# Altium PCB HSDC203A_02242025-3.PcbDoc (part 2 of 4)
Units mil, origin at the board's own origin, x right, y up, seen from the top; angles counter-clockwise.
Board outline 5612.98 x 3012.39 mil, 6 copper layers (Top Layer, GND1, Signal1, Power, GND2, Bottom Layer), stack 60.4 mil thick; 301 components, 211 nets, 1107 pads, 249 vias.
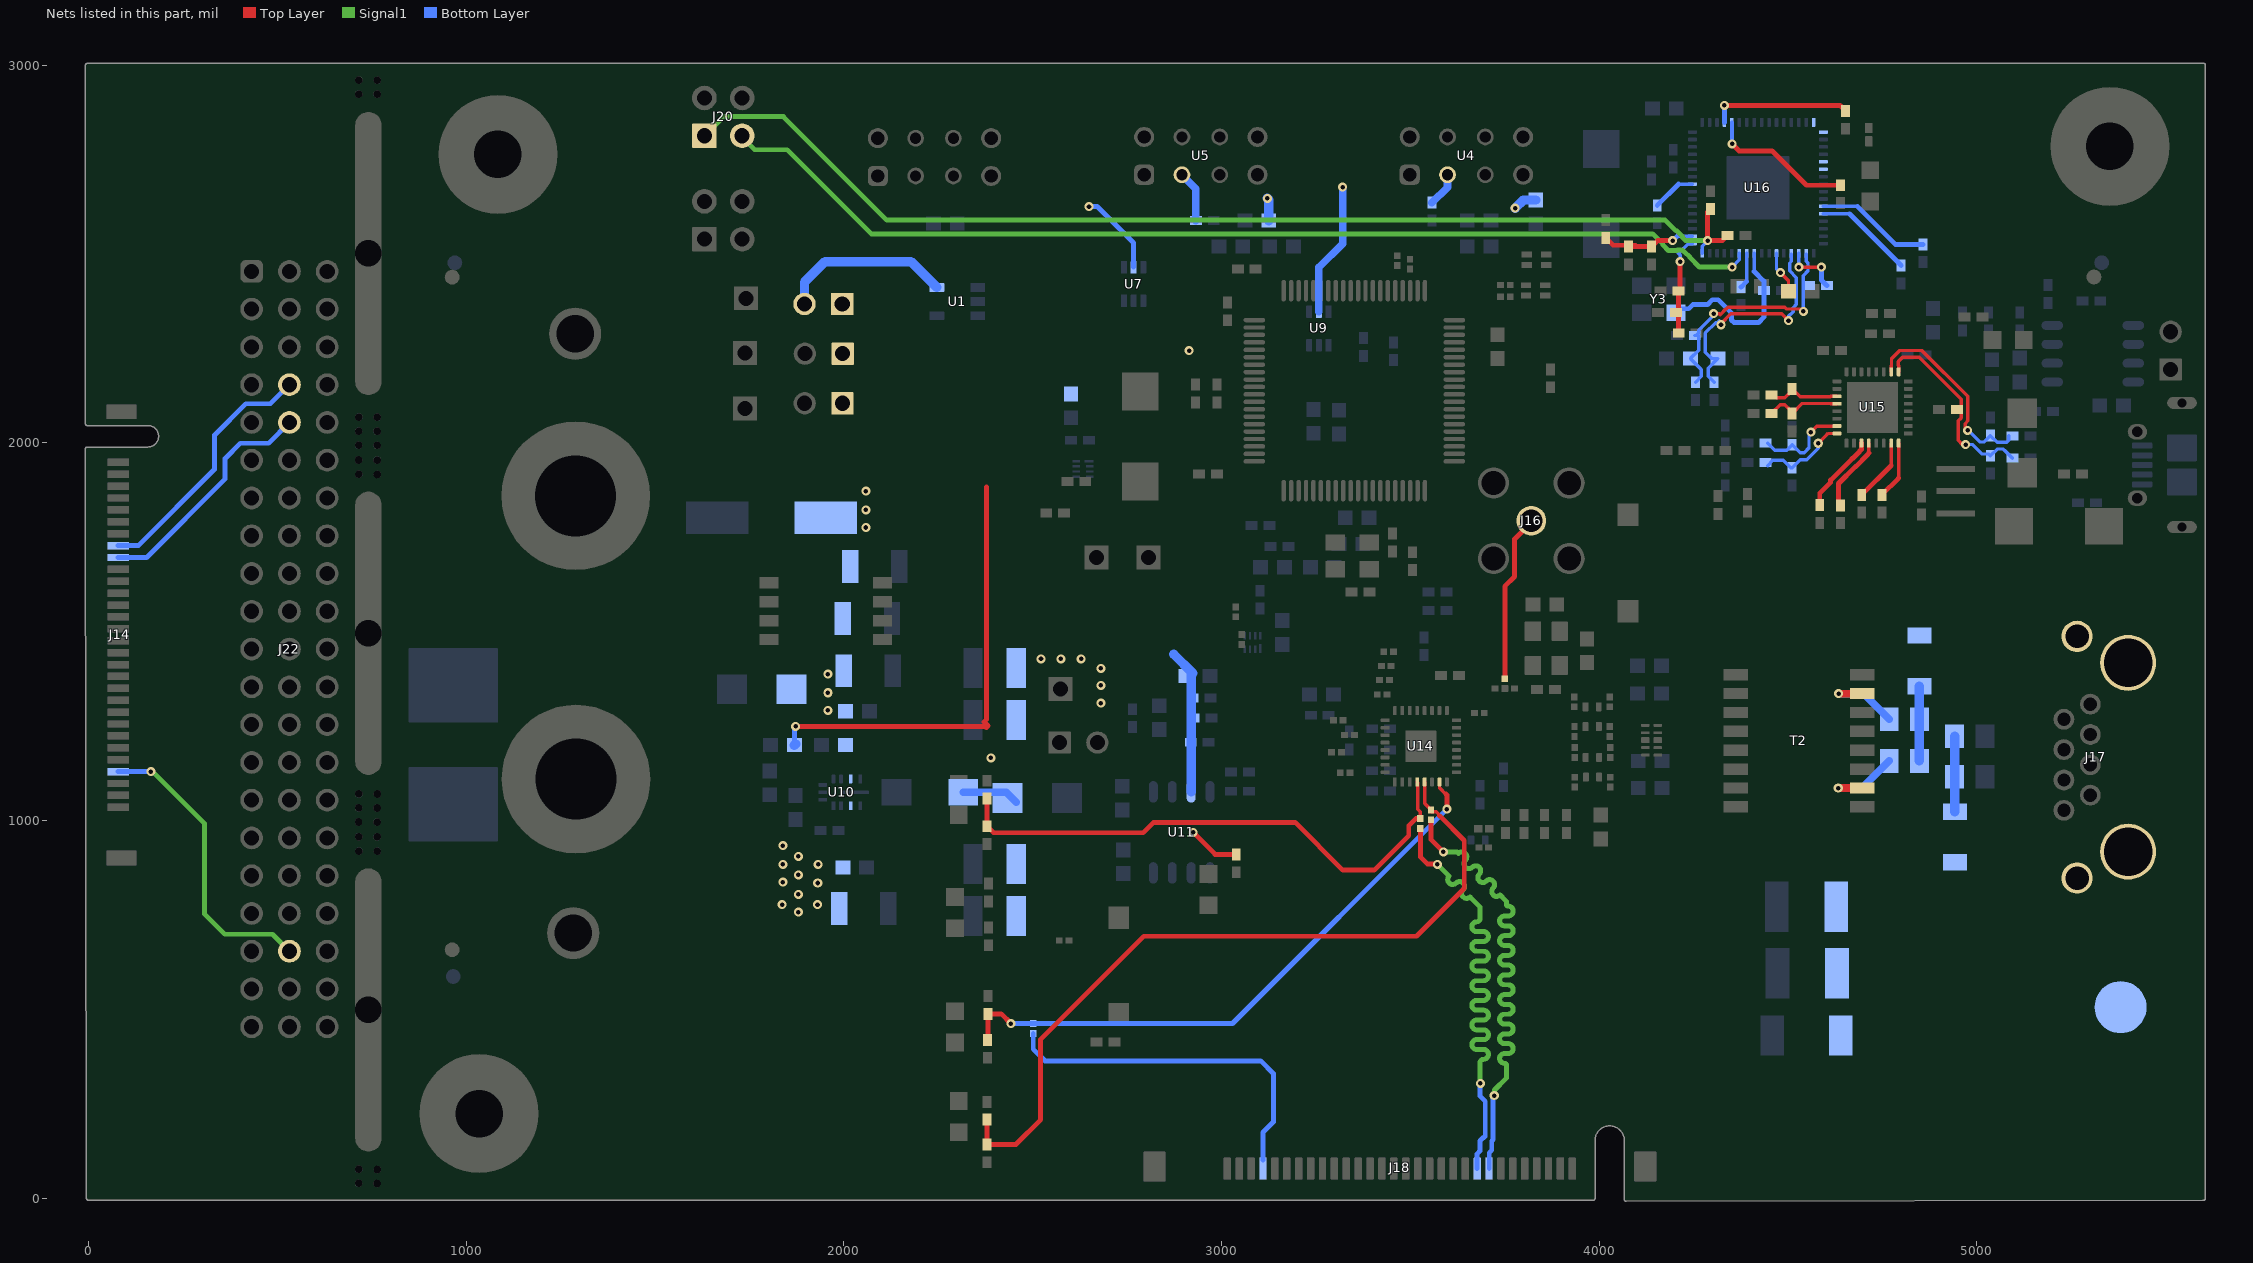
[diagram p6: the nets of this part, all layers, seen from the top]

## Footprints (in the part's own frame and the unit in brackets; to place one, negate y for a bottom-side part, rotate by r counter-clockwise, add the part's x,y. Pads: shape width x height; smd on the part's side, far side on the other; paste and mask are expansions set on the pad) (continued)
Sullins_PEC01SAAN [mm] "SULLINS"
  rect 1.6x1.6 hole 1: 1(0,0)
  silkscreen extent -1.4,-1.4 1.4,1.4, body extent -1.3,-1.3 1.3,1.3, height 8.38
SW_218-4LPST [mil] "CTS Components"
  rect 50x30 smd: 1(-150,75) 2(-150,25) 3(-150,-25) 4(-150,-75) 5(150,-75) 6(150,-25) 7(150,25) 8(150,75)
  silkscreen extent -114,-123 114,123, body extent -166,-123 166,123, height 104
TE_5-1814832-1 [mm] "SMA Straight PCB Socket Die Cast, TH"
  round 2 hole 1.5: 1(0,0)
  round 2.1 hole 1.6: 2(-2.54,2.54) 3(-2.54,-2.54) 4(2.54,-2.54) 5(2.54,2.54)
  silkscreen extent -3.2,-3.2 3.2,3.2, body extent -3.2,-3.2 3.2,3.2, height 9.5
TEC_1-406541-1 [mm] "TE Connectivity"
  round 1.4 hole 0.89: 1(3.56,-0.18) 2(2.54,1.6) 3(1.52,-0.18) 4(0.5,1.6) 5(-0.52,-0.18) 6(-1.54,1.6) 7(-2.56,-0.18) 8(-3.58,1.6)
  round 2.1 hole 1.57: 9(8.12,0.71) 10(-8.14,0.71)
  round 3.759 hole 3.251: 11(6.34,-2.72) 12(-6.36,-2.72)
  silkscreen extent -9.69,-8 9.69,8.06, body extent -9.33,-8 9.31,7.75, height 14.8
TI_Stacked_Overlay_Small [mil]
  silkscreen extent -418,-98 418,98
TSW-102-07-G-D [mm] "Samtec 100mil, 2x2, 230 mil above insulator"
  rrect6% 1.65x1.65 hole 1.016: 1(-1.27,-1.27)
  round 1.65 hole 1.016: 2(-1.27,1.27) 3(1.27,-1.27) 4(1.27,1.27)
  silkscreen extent -3.56,-2.54 2.54,2.54, body extent -2.54,-2.54 2.54,2.54, height 8.38
WEEE_Minimum [mil] "WEEElie bin"
  silkscreen extent -95,-172 99,104

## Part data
C1 C2 C5 C6 C23: library part CMP-0006356-2, "CAP, CERM, 0.1 uF, 50 V, +/- 10%, X7R, AEC-Q200 Grade 1, 0402", Cap_Case=0402, Manufacturer=MuRata, Supplier Part Number 1=490-10672-1-ND, TempCo=X7R, Tolerance_%=10%, Value1=Unknown, Value2=50V, ValueDisplayed=0.1uF
C3 C4 C43 C44: library part CMP-0007071-4, "CAP, CERM, 22 pF, 50 V, +/- 5%, C0G/NP0, AEC-Q200 Grade 1, 0603", Cap_Case=0603, Manufacturer=TDK, Supplier Part Number 1=445-5632-1-ND, TempCo=C0G/NP0, Tolerance_%=5%, Value1=Unknown, Value2=50V, ValueDisplayed=22pF
C7 C8 C90 C91: library part CMP-0083839-1, "CAP, CERM, 36 pF, 50 V,+/- 5%, C0G/NP0, 0402", Cap_Case=0402, Manufacturer="Samsung Electro-Mechanics", TempCo=C0G/NP0, Tolerance_%=5%, Value2=50V, ValueDisplayed=36pF
C9 C12: library part CMP-0006905-4, "CAP, CERM, 0.22 uF, 16 V, +80/-20%, Y5V, 0603", Cap_Case=0603, Manufacturer=Kemet, Supplier Part Number 1=399-1102-1-ND, TempCo=Y5V, Tolerance_%=80%, Value1=Unknown, Value2=16V, ValueDisplayed=0.22uF
C10: library part CMP-0007138-4, "CAP, CERM, 0.47 uF, 16 V, +/- 10%, X7R, AEC-Q200 Grade 1, 0603", Cap_Case=0603, Manufacturer=MuRata, Supplier Part Number 1=490-4775-1-ND, TempCo=X7R, Tolerance_%=10%, Value1=Unknown, Value2=16V, ValueDisplayed=0.47uF
C11: library part CMP-0007022-5, "CAP, CERM, 4.7 uF, 35 V, +/- 10%, X5R, 0603", Cap_Case=0603, Manufacturer=TDK, Supplier Part Number 1=445-9064-1-ND, TempCo=X5R, Tolerance_%=10%, Value1="0.003728 ohm", Value2=35V, ValueDisplayed=4.7uF
C13 C85: library part CMP-0011855-2, "CAP, TA, 10 uF, 35 V, +/- 10%, 0.125 ohm, SMD", Cap_Case=D, Manufacturer=AVX, Supplier Part Number 1=478-3337-1-ND, Tolerance_%=10%, Value1="0.125 ohm", Value2=35V, ValueDisplayed=10uF
C14 C15 C16 C47 C49 C57 C62 C65: library part CMP-0078241-1, "CAP, CERM, 0.1 µF, 10 V,+/- 10%, X7R, 0402", Cap_Case=0402, Manufacturer=Kemet, Supplier Part Number 1=399-3520-1-ND, TempCo=X7R, Tolerance_%=10%, Value2=10V, ValueDisplayed=0.1µF
C17 C83: library part CMP-0006254-2, "CAP, CERM, 1000 pF, 50 V, +/- 5%, C0G/NP0, 0402", Cap_Case=0402, Manufacturer=TDK, Supplier Part Number 1=445-13785-1-ND, TempCo=C0G/NP0, Tolerance_%=5%, Value1=Unknown, Value2=50V, ValueDisplayed=1000pF
C18: library part CMP-0011279-3, "CAP, AL, 100 uF, 50 V, +/- 20%, SMD", Cap_Case=HA0, Manufacturer=Chemi-Con, Supplier Part Number 1=565-2252-1-ND, Tolerance_%=20%, Value1=Unknown, Value2=50V, ValueDisplayed=100uF
C19 C21: library part CMP-0009162-2, "CAP, CERM, 4.7 uF, 50 V, +/- 10%, X7R, AEC-Q200 Grade 1, 1210", Cap_Case=1210_280, Manufacturer=TDK, Supplier Part Number 1=445-6999-1-ND, TempCo=X7R, Tolerance_%=10%, Value1="0.003166 ohm", Value2=50V, ValueDisplayed=4.7uF
C20 C22: library part CMP-0007094-5, "CAP, CERM, 0.22 uF, 50 V, +/- 10%, X7R, AEC-Q200 Grade 1, 0603", Cap_Case=0603, Manufacturer=TDK, Supplier Part Number 1=445-6926-1-ND, TempCo=X7R, Tolerance_%=10%, Value1="0.021699 ohm", Value2=50V, ValueDisplayed=0.22uF
C24: library part CMP-0009154-2, "CAP, CERM, 22 uF, 16 V, +/- 20%, X7R, AEC-Q200 Grade 1, 1210", Cap_Case=1210_280, Manufacturer=TDK, Supplier Part Number 1=445-5723-1-ND, TempCo=X7R, Tolerance_%=20%, Value1="0.002582 ohm", Value2=16V, ValueDisplayed=22uF
C25: library part CMP-0009155-2, "CAP, CERM, 10 uF, 25 V, +/- 20%, X7R, AEC-Q200 Grade 1, 1210", Cap_Case=1210, Manufacturer=TDK, Supplier Part Number 1=445-5720-1-ND, TempCo=X7R, Tolerance_%=20%, Value1=Unknown, Value2=25V, ValueDisplayed=10uF
C26: library part CMP-0007067-4, "CAP, CERM, 1 uF, 35 V, +/- 10%, X7R, AEC-Q200 Grade 1, 0603", Cap_Case=0603, Manufacturer=TDK, Supplier Part Number 1=445-174215-1-ND, TempCo=X7R, Tolerance_%=10%, Value1="0.005522 ohm", Value2=35V, ValueDisplayed=1uF
C27 C28 C29 C30: library part CMP-0080552-1, "CAP, CERM, 22 µF, 25 V,+/- 10%, X7R, AEC-Q200 Grade 1, 1210", Cap_Case=1210, Manufacturer="Taiyo Yuden", Supplier Part Number 1=587-5949-1-ND, TempCo=X7R, Tolerance_%=10%, Value2=25V, ValueDisplayed=22µF
C31 C37: library part CMP-0006620-2, "CAP, CERM, 1 uF, 35 V, +/- 20%, X5R, 0402", Cap_Case=0402, Manufacturer=MuRata, Supplier Part Number 1=490-10020-1-ND, TempCo=X5R, Tolerance_%=20%, Value1=Unknown, Value2=35V, ValueDisplayed=1uF
C32 C35 C38 C41: library part CMP-0007355-6, "CAP, CERM, 10 uF, 35 V, +/- 20%, X5R, 0603", Cap_Case=0603, Manufacturer=Murata, TempCo=X5R, Tolerance_%=20%, Value1=Unknown, Value2=35V, ValueDisplayed=10uF
C33 C34 C39 C40: library part CMP-0006526-2, "CAP, CERM, 2.2 uF, 16 V, +/- 10%, X6S, 0402", Cap_Case=0402, Manufacturer=MuRata, Supplier Part Number 1=GRM155C81C225KE11D-ND, TempCo=X6S, Tolerance_%=10%, Value1=Unknown, Value2=16V, ValueDisplayed=2.2uF
C36 C42: library part CMP-0006360-2, "CAP, CERM, 470 pF, 50 V, +/- 10%, X7R, AEC-Q200 Grade 1, 0402", Cap_Case=0402, Manufacturer=MuRata, Supplier Part Number 1=490-4913-1-ND, TempCo=X7R, Tolerance_%=10%, Value1=Unknown, Value2=50V, ValueDisplayed=470pF
C45 C55: library part CMP-0006862-5, "CAP, CERM, 0.1 uF, 10 V, +/- 10%, X7R, 0603", Cap_Case=0603, Manufacturer=Kemet, Supplier Part Number 1=399-1095-1-ND, TempCo=X7R, Tolerance_%=10%, Value1=Unknown, Value2=10V, ValueDisplayed=0.1uF
C46 C56: library part CMP-0007195-4, "CAP, CERM, 2000 pF, 50 V, +/- 5%, C0G/NP0, 0603", Cap_Case=0603, Manufacturer=MuRata, Supplier Part Number 1=490-1458-1-ND, TempCo=C0G/NP0, Tolerance_%=5%, Value1=Unknown, Value2=50V, ValueDisplayed=2000pF
C48 C50: library part CMP-0006340-2, "CAP, CERM, 10 uF, 6.3 V, +/- 20%, X5R, 0402", Cap_Case=0402, Manufacturer="Samsung Electro-Mechanics", TempCo=X5R, Tolerance_%=20%, Value1=Unknown, Value2=6.3V, ValueDisplayed=10uF
C51 C53 C60: library part CMP-0006227-2, "CAP, CERM, 0.01 uF, 16 V, +/- 10%, X7R, 0402", Cap_Case=0402, Manufacturer="Wurth Elektronik", Supplier Part Number 1=710-885012205031, TempCo=X7R, Tolerance_%=10%, Value1=Unknown, Value2=16V, ValueDisplayed=0.01uF
C52 C54: library part CMP-0064947-2, "CAP, CERM, 1 uF, 6.3 V,+/- 10%, X7R, 0402", Cap_Case=0402, Manufacturer=MuRata, Supplier Part Number 1=490-10024-1-ND, TempCo=X7R, Tolerance_%=10%, Value1=Unknown, Value2=6.3V, ValueDisplayed=1uF
C58 C59: library part CMP-0008579-2, "CAP, CERM, 1000 pF, 2000 V, +/- 10%, X7R, AEC-Q200 Grade 1, 1206", Cap_Case=1206, Manufacturer=Kemet, Supplier Part Number 1=399-12976-1-ND, TempCo=X7R, Tolerance_%=10%, Value1=Unknown, Value2=2000V, ValueDisplayed=1000pF
C61 C63: library part CMP-0009295-2, "CAP, CERM, 4700 pF, 2000 V, +/- 10%, X7R, 1812", Cap_Case=1812, Manufacturer=AVX, Supplier Part Number 1=478-3003-1-ND, TempCo=X7R, Tolerance_%=10%, Value1=Unknown, Value2=2000V, ValueDisplayed=4700pF
C64: library part CMP-0011708-2, "CAP, TA, 4.7 uF, 35 V, +/- 10%, 1.3 ohm, SMD", Cap_Case=D, Manufacturer=Vishay-Sprague, Supplier Part Number 1=718-1084-1-ND, Tolerance_%=10%, Value1="1.3 ohm", Value2=35V, ValueDisplayed=4.7uF
C66 C67 C68 C69 C72 C73: library part CMP-0860896-1, "CAP, CERM, 22 pF, 50 V,+/- 5%, C0G/NP0, 0402", Cap_Case=0402, Manufacturer=TDK, TempCo=C0G/NP0, Tolerance_%=5%, Value2=50V, ValueDisplayed=22pF
C70 C71 C75 C76: library part CMP-0007074-4, "CAP, CERM, 10 pF, 50 V, +/- 5%, C0G/NP0, 0603", Cap_Case=0603, Manufacturer=TDK, Supplier Part Number 1=445-12387-1-ND, TempCo=C0G/NP0, Tolerance_%=5%, Value1=Unknown, Value2=50V, ValueDisplayed=10pF
C74 C77 C78 C86 C87: library part CMP-0085850-1, "CAP, CERM, 0.1 µF, 16 V,+/- 10%, X7R, 0402", Cap_Case=0402, Manufacturer=Walsin, TempCo=X7R, Tolerance_%=10%, Value2=16V, ValueDisplayed=0.1µF
C79 C80: library part CMP-0860833-1, "CAP, CERM, 33 pF, 50 V,+/- 5%, C0G/NP0, AEC-Q200 Grade 1, 0402", Cap_Case=0402, Manufacturer=MuRata, TempCo=C0G/NP0, Tolerance_%=5%, Value2=50V, ValueDisplayed=33pF
C81 C84: library part CMP-0860899-1, "CAP, CERM, 0.22 µF, 50 V,+/- 10%, X5R, 0603", Cap_Case=0603, Manufacturer="Samsung Electro-Mechanics", TempCo=X5R, Tolerance_%=10%, Value2=50V, ValueDisplayed=0.22µF
C82: library part CMP-0007096-4, "CAP, CERM, 0.47 uF, 50 V, +/- 10%, X7R, AEC-Q200 Grade 1, 0603", Cap_Case=0603, Manufacturer=TDK, Supplier Part Number 1=810-CGA3E3X7R1H474K080AB, TempCo=X7R, Tolerance_%=10%, Value1="0.01064 ohm", Value2=50V, ValueDisplayed=0.47uF
C88: library part CMP-0093676-1, "Chip Multilayer Ceramic Capacitors for General Purpose, 0402, 2.2uF, X7R, 15%, 10%, 10V", Manufacturer=Murata, Operating Temperature Range="-55°C to +125°C", TempCo=15%, Temperature Characteristic=X7R, Tolerance_%=10%, ValueDisplayed=2.2uF
C89 C92 C93 C94 C95 C96 C97 C98: library part CMP-0009653-3, "CAP, CERM, 330 pF, 50 V, +/- 10%, X7R, AEC-Q200 Grade 1, 0201", Cap_Case=0201_033, Manufacturer=TDK, Supplier Part Number 1=445-12111-1-ND, TempCo=X7R, Tolerance_%=10%, Value1="8.05302 ohm", Value2=50V, ValueDisplayed=330pF
D1 D6: library part CMP-0002934-2, "LED, Rg, SMD", Color=RG, Manufacturer=Avago, Supplier Part Number 1=516-1419-1-ND, Value1=W, Value2=2.2V
D2 D3 D7: library part CMP-0028762-2, "Diode, Schottky, 60 V, 1 A, AEC-Q101, SMA", Manufacturer="ON Semiconductor", Value1=1A, Value2=0.51V
D4: library part CMP-0077734-1, "LED, Orange, SMD", Color=Orange, Manufacturer=Kingbright, Power_TotalModule=75mW, Supplier Part Number 1=754-1103-1-ND, Value1=.075W, Value2=2.1V
D5 LD1 LD2 LD3 LD4 LD5 LD6: library part CMP-0002917-2, "LED, Green, SMD", Color=Green, Manufacturer=Everlight, Value1=W, Value2=2.1V
FID1 FID2 FID3 FID4 FID5 FID6: library part CMP-0077181-1, "Fiducial mark.  There is nothing to buy or mount.", Manufacturer=N/A
H1 H2 H3: library part CMP-0003617-1, "Machine Screw, Round, #4-40 x 1/4, Nylon, Philips panhead", Manufacturer="B&F Fastener Supply", Supplier Part Number 1=H542-ND
H5 H6 H7 H8: library part CMP-0003611-1, "Standoff, Hex, 1\"L #4-40 Nylon", Manufacturer=Keystone, Supplier Part Number 1=36-1902E-ND
J1: library part CMP-0054706-1, "Header, 1x1, Tin, TH", Color=Black, Current_A=3A, Manufacturer="Sullins Connector Solutions", PartNumber=PEC01SAAN, Supplier Part Number 1=S1012E-01-ND, Voltage_V=1.8kV
J2 J10 J11 J12 J13: library part CMP-0054706-1, "Header, 1x1, Tin, TH", Color=Black, Current_A=3A, Manufacturer="Sullins Connector Solutions", Supplier Part Number 1=S1012E-01-ND, Voltage_V=1.8kV
J3 J20: library part CMP-0075404-1, "Header, 100mil, 2x2, Gold, TH", Color=Black, Current_A=6.3A, Manufacturer=Samtec, Supplier Part Number 1=SAM1028-02-ND, Voltage_V=550V
J4 J5 J24: library part CMP-0055113-1, "Terminal, Turret, TH, Double", Manufacturer=Keystone, Supplier Part Number 1=36-1502-2-ND
J6 J7 J8 J9 J23: library part CMP-0002337-1, "Header, 100mil, 2x1, Tin, TH", Color=Black, Current_A=3A, Manufacturer="Sullins Connector Solutions", Supplier Part Number 1=S1012E-02-ND, Voltage_V=1.8kV
J14: library part CMP-0055619-1, "Receptacle, 0.8mm, 30x2, Tin, Edge mount", Color=Black, Current_A=2.2A, Manufacturer=Samtec, Supplier Part Number 1=33R2583, Voltage_V=200V
J15 J21: library part CMP-0055165-2, "Standard Banana Jack, Uninsulated, 5.5mm", Manufacturer=Keystone, Supplier Part Number 1=36-575-4-ND
J16: library part CMP-0054990-1, "SMA Straight PCB Socket Die Cast, 50 Ohm, TH", Manufacturer="TE Connectivity", Supplier Part Number 1=A97594-ND
J17: library part CMP-0054918-1, "RJ45, No LED, tab up, R/A, TH", Color=Black, Manufacturer="TE Connectivity", Supplier Part Number 1=A97716-ND
J18: library part CMP-0055720-1, "Receptacle, 0.8mm, 30x2, Gold, Edge Mount", Current_A=2.2A, Manufacturer=Samtec, Supplier Part Number 1=ERF8-030-01-L-D-EM2-TR-ND, Voltage_V=200V
J19: library part CMP-0055301-1, "Connector, Receptacle, Micro-USB Type AB, R/A, Bottom Mount SMT", Manufacturer=Molex, Supplier Part Number 1=WM17143CT-ND
J22: library part CMP-0084401-1, "Header, 2.54mm, 21x3, Gold, TH", Color=Natural, Manufacturer=Samtec
L1: library part CMP-0056947-1, "Inductor, Shielded, Ferrite, 10 uH, 2.75 A, 0.128 ohm, SMD", Manufacturer=Bourns, Supplier Part Number 1=652-SRP5030T-100M, Value1="0.128 ohm", Value2=2.75A, ValueDisplayed=10uH
Logo1: library part CMP-0074844-1
Logo2: library part CMP-0074838-1, "Texas Instrument Corporate Signature"
Logo3: library part CMP-0074847-1, "FCC_disclaimer"
Logo4: library part CMP-0074769-1
R1 R2: library part CMP-0025750-4, "RES, 200 k, 5%, 0.1 W, AEC-Q200 Grade 0, 0603", Manufacturer=Vishay-Dale, Power_W=100mW, Supplier Part Number 1=541-200KGCT-ND, TempCo="200 ppm/C", Tolerance_%=5%, Value2=0.1W, Value_Code=200k
R3 R4: library part CMP-0025879-3, "RES, 2.2 k, 5%, 0.1 W, AEC-Q200 Grade 0, 0603", Manufacturer=Panasonic, Power_W=100mW, Supplier Part Number 1=P2.2KGCT-ND, TempCo="200 ppm/C", Tolerance_%=5%, Value2=0.1W, Value_Code=2k20, ValueDisplayed=2.2k
R5: library part CMP-0021993-5, "RES, 102, 1%, 0.1 W, AEC-Q200 Grade 0, 0603", Manufacturer=Vishay-Dale, Power_W=100mW, Supplier Part Number 1=541-102HCT-ND, TempCo="100 ppm/C", Tolerance_%=1%, Value2=0.1W, Value_Code=102R, ValueDisplayed=102
R6 R27 R30 R32 R35: library part CMP-0025874-4, "RES, 0, 5%, 0.1 W, AEC-Q200 Grade 0, 0603", Manufacturer=Panasonic, Power_W=100mW, Supplier Part Number 1=P0.0GCT-ND, TempCo="600 ppm/C", Tolerance_%=5%, Value2=0.1W, Value_Code=0000, ValueDisplayed=0
R7: library part CMP-0025785-4, "RES, 330, 5%, 0.1 W, AEC-Q200 Grade 0, 0603", Manufacturer=Vishay-Dale, Power_W=100mW, Supplier Part Number 1=541-330GCT-ND, TempCo="200 ppm/C", Tolerance_%=5%, Value2=0.1W, Value_Code=330R, ValueDisplayed=330
R8 R9 R10 R11 R109 R110: library part CMP-0026992-3, "RES, 0, 5%, 0.1 W, AEC-Q200 Grade 0, 0402", Manufacturer=Panasonic, Power_W=100mW, Supplier Part Number 1=P0.0JCT-ND, TempCo="600 ppm/C", Tolerance_%=5%, Value2=0.1W, Value_Code=0000, ValueDisplayed=0
R12 R26: library part CMP-0022237-4, "RES, 24.9 k, 1%, 0.1 W, AEC-Q200 Grade 0, 0603", Manufacturer=Vishay-Dale, Power_W=100mW, Supplier Part Number 1=541-24.9KHCT-ND, TempCo="100 ppm/C", Tolerance_%=1%, Value2=0.1W, Value_Code=24k9, ValueDisplayed=24.9k
R13 R23: library part CMP-0026822-3, "RES, 0, 5%, 0.063 W, AEC-Q200 Grade 0, 0402", Manufacturer=Vishay-Dale, Power_W=63mW, Supplier Part Number 1=541-0.0JCT-ND, TempCo="200 ppm/C", Tolerance_%=5%, Value2=0.063W, Value_Code=0000, ValueDisplayed=0
R14 R15 R16 R17 R49: library part CMP-0027127-1, "RES, 470, 5%, 0.05 W, 0201", Manufacturer="Yageo America", Power_W=50mW, Supplier Part Number 1=311-470NCT-ND, TempCo="200 ppm/C", Tolerance_%=5%, Value2=0.05W, Value_Code=470R, ValueDisplayed=470
R18 R19 R37 R40 R42 R78 R96 R97 R98 R99 R100 R101 R102 R103 R104 R107 R108: library part CMP-0027008-4, "RES, 0, 5%, 0.05 W, 0201", Manufacturer=Vishay-Dale, Power_W=50mW, Supplier Part Number 1=72M6743, TempCo=ppm/C, Tolerance_%=5%, Value2=0.05W, Value_Code=0000, ValueDisplayed=0
R20 R77: library part CMP-0026085-3, "RES, 1.40 k, 1%, 0.063 W, AEC-Q200 Grade 0, 0402", Manufacturer=Vishay-Dale, Power_W=63mW, Supplier Part Number 1=541-1.40KLCT-ND, TempCo="100 ppm/C", Tolerance_%=1%, Value2=0.063W, Value_Code=1k40, ValueDisplayed=1.40k
R21 R81: library part CMP-0026100-2, "RES, 1.00 M, 1%, 0.063 W, AEC-Q200 Grade 0, 0402", Manufacturer=Vishay-Dale, Power_W=63mW, Supplier Part Number 1=541-1.00MLCT-ND, TempCo="100 ppm/C", Tolerance_%=1%, Value2=0.063W, Value_Code=1M00, ValueDisplayed=1.00M
R22 R79 R93: library part CMP-0026935-3, "RES, 47 k, 5%, 0.063 W, AEC-Q200 Grade 0, 0402", Manufacturer=Vishay-Dale, Power_W=63mW, Supplier Part Number 1=541-47KJCT-ND, TempCo="200 ppm/C", Tolerance_%=5%, Value2=0.063W, Value_Code=47k0, ValueDisplayed=47k
R24: library part CMP-0023343-3, "RES, 0, 1%, 0.1 W, AEC-Q200 Grade 0, 0603", Manufacturer="Stackpole Electronics Inc", Power_W=100mW, Supplier Part Number 1=RMCF0603ZT0R00CT-ND, TempCo=ppm/C, Tolerance_%=1%, Value2=0.1W, Value_Code=0
R25: library part CMP-0021990-4, "RES, 100 k, 1%, 0.1 W, AEC-Q200 Grade 0, 0603", Manufacturer=Vishay-Dale, Power_W=100mW, Supplier Part Number 1=541-100KHCT-ND, TempCo="100 ppm/C", Tolerance_%=1%, Value2=0.1W, Value_Code=100k
R28 R33: library part CMP-0026768-2, "RES, 100 k, 0.5%, 0.063 W, AEC-Q200 Grade 0, 0402", Manufacturer=Vishay-Dale, Power_W=63mW, Supplier Part Number 1=541-100KAVCT-ND, TempCo="50 ppm/C", Tolerance_%=0.5%, Value2=0.063W, Value_Code=100k
R29 R34 R53 R55 R57 R58 R86 R87: library part CMP-0026934-3, "RES, 470, 5%, 0.063 W, AEC-Q200 Grade 0, 0402", Manufacturer=Vishay-Dale, Power_W=63mW, Supplier Part Number 1=541-470JCT-ND, TempCo="200 ppm/C", Tolerance_%=5%, Value2=0.063W, Value_Code=470R, ValueDisplayed=470
R31 R36: library part CMP-0026036-3, "RES, 165 k, 1%, 0.063 W, AEC-Q200 Grade 0, 0402", Manufacturer=Vishay-Dale, Power_W=63mW, Supplier Part Number 1=541-165KLCT-ND, TempCo="100 ppm/C", Tolerance_%=1%, Value2=0.063W, Value_Code=165k
R38 R94 R95: library part CMP-0027004-2, "RES, 0, 5%, 0.063 W, 0402", Manufacturer="Yageo America", Power_W=63mW, Supplier Part Number 1=311-0.0JRCT-ND, TempCo="200 ppm/C", Tolerance_%=5%, Value2=0.063W, Value_Code=0000, ValueDisplayed=0
R39: library part CMP-0026727-1, "RES, 1.00 M, 1%, 0.063 W, 0402", Manufacturer="Yageo America", Power_W=63mW, Supplier Part Number 1=311-1.00MLRCT-ND, TempCo="100 ppm/C", Tolerance_%=1%, Value2=0.063W, Value_Code=1M00, ValueDisplayed=1.00M
R41 R88: library part CMP-0025697-4, "RES, 0, 5%, 0.1 W, AEC-Q200 Grade 0, 0603", Manufacturer=Vishay-Dale, Power_W=100mW, Supplier Part Number 1=541-0.0GCT-ND, TempCo="200 ppm/C", Tolerance_%=5%, Value2=0.1W, Value_Code=0000, ValueDisplayed=0
R43 R44 R45 R46: library part CMP-0021425-3, "RES, 75.0, 1%, 0.125 W, AEC-Q200 Grade 0, 0805", Manufacturer=Vishay-Dale, Power_W=125mW, Supplier Part Number 1=541-75.0CCT-ND, TempCo="100 ppm/C", Tolerance_%=1%, Value2=0.125W, Value_Code=75R0, ValueDisplayed=75.0
R47: library part CMP-0026890-5, "RES, 2.2 k, 5%, 0.063 W, AEC-Q200 Grade 0, 0402", Manufacturer=Vishay-Dale, Power_W=63mW, Supplier Part Number 1=541-2.2KJCT-ND, TempCo="200 ppm/C", Tolerance_%=5%, Value2=0.063W, Value_Code=2k20, ValueDisplayed=2.2k
R48: library part CMP-0026515-2, "RES, 6.49 k, 1%, 0.063 W, AEC-Q200 Grade 0, 0402", Manufacturer=Vishay-Dale, Power_W=63mW, Supplier Part Number 1=541-6.49KLCT-ND, TempCo="100 ppm/C", Tolerance_%=1%, Value2=0.063W, Value_Code=6k49, ValueDisplayed=6.49k
R50: library part CMP-0065361-1, "RES, 0, 5%, .05 W, AEC-Q200 Grade 0, 0201", Manufacturer=Panasonic, Power_W=50mW, Supplier Part Number 1=P15979CT-ND, TempCo=ppm/C, Tolerance_%=5%, Value2=.05W, Value_Code=0000, ValueDisplayed=0
R51: library part CMP-0016200-2, "RES, 10 M, 5%, 0.5 W, 2010", Manufacturer="TT Electronics/IRC", Power_W=500mW, Supplier Part Number 1=756-HVC2010-10MJT3, TempCo="100 ppm/C", Tolerance_%=5%, Value2=0.5W, Value_Code=10M0, ValueDisplayed=10M
R52 R111 R112 R113: library part CMP-0120020-1, "0 Ohms Jumper Chip Resistor 0402 (1005 Metric) Metal Element", Digikey Part Number=36-5113-1-ND, Manufacturer="Keystone Electronics", Mouser Part Number=534-5113, Operating Temperature Range=to
R54 R56 R59 R60 R115: library part CMP-0026756-1, "RES, 1.50 k, 1%, 0.063 W, AEC-Q200 Grade 0, 0402", Manufacturer="Stackpole Electronics Inc", Power_W=63mW, Supplier Part Number 1=RMCF0402FT1K50CT-ND, TempCo="100 ppm/C", Tolerance_%=1%, Value2=0.063W, Value_Code=1k50, ValueDisplayed=1.50k
R61 R106: library part CMP-0026088-3, "RES, 1.50 k, 1%, 0.063 W, AEC-Q200 Grade 0, 0402", Manufacturer=Vishay-Dale, Power_W=63mW, Supplier Part Number 1=541-1.50KLCT-ND, TempCo="100 ppm/C", Tolerance_%=1%, Value2=0.063W, Value_Code=1k50, ValueDisplayed=1.50k
R62: library part CMP-0026825-5, "RES, 10 k, 5%, 0.063 W, AEC-Q200 Grade 0, 0402", Manufacturer=Vishay-Dale, Power_W=63mW, Supplier Part Number 1=541-10KJCT-ND, TempCo="200 ppm/C", Tolerance_%=5%, Value2=0.063W, Value_Code=10k0, ValueDisplayed=10k
R63 R66 R76 R80: library part CMP-0026888-3, "RES, 27, 5%, 0.063 W, AEC-Q200 Grade 0, 0402", Manufacturer=Vishay-Dale, Power_W=63mW, Supplier Part Number 1=541-27JCT-ND, TempCo="200 ppm/C", Tolerance_%=5%, Value2=0.063W, Value_Code=27R0, ValueDisplayed=27
R64 R65 R67 R68 R71 R72: library part CMP-0026880-3, "RES, 22, 5%, 0.063 W, AEC-Q200 Grade 0, 0402", Manufacturer=Vishay-Dale, Power_W=63mW, Supplier Part Number 1=541-22JCT-ND, TempCo="200 ppm/C", Tolerance_%=5%, Value2=0.063W, Value_Code=22R0, ValueDisplayed=22
R69 R70 R73 R74 R82 R83 R84 R85: library part CMP-0026027-3, "RES, 15.0 k, 1%, 0.063 W, AEC-Q200 Grade 0, 0402", Manufacturer=Vishay-Dale, Power_W=63mW, Supplier Part Number 1=541-15.0KLCT-ND, TempCo="100 ppm/C", Tolerance_%=1%, Value2=0.063W, Value_Code=15k0, ValueDisplayed=15.0k
R75: library part CMP-0026908-3, "RES, 33, 5%, 0.063 W, AEC-Q200 Grade 0, 0402", Manufacturer=Vishay-Dale, Power_W=63mW, Supplier Part Number 1=541-33JCT-ND, TempCo="200 ppm/C", Tolerance_%=5%, Value2=0.063W, Value_Code=33R0, ValueDisplayed=33
R89: library part CMP-0026881-2, "RES, 240 k, 5%, 0.063 W, AEC-Q200 Grade 0, 0402", Manufacturer=Vishay-Dale, Power_W=63mW, Supplier Part Number 1=541-240KJCT-ND, TempCo="200 ppm/C", Tolerance_%=5%, Value2=0.063W, Value_Code=240k
R90 R92: library part CMP-0026877-2, "RES, 220 k, 5%, 0.063 W, AEC-Q200 Grade 0, 0402", Manufacturer=Vishay-Dale, Power_W=63mW, Supplier Part Number 1=541-220KJCT-ND, TempCo="200 ppm/C", Tolerance_%=5%, Value2=0.063W, Value_Code=220k
R91: library part CMP-0026840-2, "RES, 150 k, 5%, 0.063 W, AEC-Q200 Grade 0, 0402", Manufacturer=Vishay-Dale, Power_W=63mW, Supplier Part Number 1=541-150KJCT-ND, TempCo="200 ppm/C", Tolerance_%=5%, Value2=0.063W, Value_Code=150k
R105: library part CMP-0027010-2, "RES, 2.2 k, 5%, 0.05 W, 0201", Manufacturer=Vishay-Dale, Power_W=50mW, Supplier Part Number 1=541-2.2KAGCT-ND, TempCo="200 ppm/C", Tolerance_%=5%, Value2=0.05W, Value_Code=2k20, ValueDisplayed=2.2k
R114: library part CMP-0026237-2, "RES, 2.49 k, 1%, 0.063 W, AEC-Q200 Grade 0, 0402", Manufacturer=Vishay-Dale, Power_W=63mW, Supplier Part Number 1=541-2.49KLCT-ND, TempCo="100 ppm/C", Tolerance_%=1%, Value2=0.063W, Value_Code=2k49, ValueDisplayed=2.49k
S1: library part CMP-0002128-2, "Switch, Slide, SPST 4 poles, SMT", CurrentRating_mA=25A, Manufacturer="CTS Electrocomponents", Supplier Part Number 1=CT2184LPST-ND
S2 S3: library part CMP-0002170-2, "Switch, Normally open, 2.3N force, 200k operations, SMD", CurrentRating_mA=1.001kA, Manufacturer="C&K Components"
SH-J1 SH-J2 SH-J3 SH-J4: library part CMP-0078738-1, "Single Operation 2.54mm Pitch Open Top Jumper Socket", Manufacturer=Harwin, Supplier Part Number 1=952-2881-ND
T2: library part CMP-0030425-2, "Transformer, 350 uH, SMT", Manufacturer="Pulse Engineering", Supplier Part Number 1=553-2208-1-ND, ValueDisplayed=350uH
U1: library part CMP-0051649-3, "Automotive Catalog Single Inverter, DBV0005A, LARGE T&R", Alternate Manufacturer="Texas Instruments", F @ Nom Voltage(Max)(Mhz)=150, Generic Part Number=SN74LVC1G04-Q1, ICC @ Nom Voltage(Max)(mA)=0.01, Operating Temperature Range="-40 to 125 C", Rating=Automotive, tpd @ Nom Voltage(Max)(ns)=7.5,5.2,4.2,3.7, Voltage(Nom)(V)=1.8,2.5,3.3,5
U2 U3: library part CMP-0066434-1, "Dual Bidirectional Multi-Voltage Level Translator, DQE0008A (X2SON-8)", Alternate Manufacturer="Texas Instruments"
U4 U5: library part CMP-0079203-2, "Fiber Optic Receiver 5MBd, TH", Manufacturer="Broadcom Limited"
U6: library part CMP-0079202-2, "Fiber Optic Transmitter 820nm, TH", Manufacturer="Broadcom Limited"
U7 U9: library part CMP-0860319-1, "1-ch, 2:1 general-purpose analog multiplexer with 1.8-V logic control, DCK0006A (SOT-SC70-6)", Alternate Manufacturer="Texas Instruments", Operating Temperature Range="-40 to 125 C", Rating=Catalog
U8: library part CMP-0038965-1, "25 MHz Mixed Signal Microcontroller with 128 KB Flash, 8192 B SRAM and 63 GPIOs, -40 to 85 degC, 80-pin QFP (PN), Green (RoHS & no Sb/Br)", Frequency(MHz)=25, Manufacturer="Texas Instruments", Temp Sensor=Yes
U10: library part CMP-0081171-4, "3.8-V to 36-V 2-A Synchronous Step-Down Voltage Regulator, RNX0012B (VQFN-HR-12)", Alternate Manufacturer="Texas Instruments", Alternate PartNumber=LMR33620ARNXR, Operating Temperature Range="-40 to 125 C", Rating=Catalog
U11 U12: library part CMP-0036447-1, "Single Output Low Noise LDO, 500 mA, Adjustable 1.3 to 6.5 V Output, 2.5 to 16 V Input, 8-pin SOIC (D), -40 to 125 degC, Green (RoHS & no Sb/Br)", Manufacturer="Texas Instruments", Rating=Catalog
U13: library part CMP-0073613-3, "4-Channel Ultra-Low-Capacitance IEC ESD Protection Diode, DQA0010A (USON-10)", Alternate Manufacturer="Texas Instruments"
U14: library part CMP-0124715-1, "Deterministic, Low-Latency, Low-Power, 10/100 Mbps, Industrial Ethernet PHY", Manufacturer="Texas Instruments", Max Supply Voltage=3.6V, Min Supply Voltage=1.62V, Operating Temperature Range="-40°C to +85°C"
U15: library part CMP-0033743-2, "4-Port Full-Speed USB Hub, 3.3V, -40 to 85 degC, 32-Pin QFN (RHB), Green (RoHS & no Sb/Br)", Manufacturer="Texas Instruments", Supply Voltage(s)(V)=3.3
U16: library part CMP-0039268-4, "16-Bit Ultra-Low-Power Microcontroller, 128KB Flash, 8KB RAM, USB, 12Bit ADC, 2 USCIs, 32Bit HW MPY, RGC0064B (VQFN-64)", Frequency(MHz)=25, Manufacturer="Texas Instruments", Operating Temperature Range="-40 to 85 C", Rating=Catalog, Temp Sensor=Yes
XF1: library part CMP-0077258-1, "FUSE HLDR CARTRIDGE 125V 5A SMD", Manufacturer=Schurter, Supplier Part Number 1=486-1991-ND
XTAL1: library part CMP-0079863-1, "Crystal, 25 MHz, 20 ppm, AEC-Q200 Grade 1, SMD", Frequency_Fixed=25MHz, Frequency Stability="50 ppm", Frequency Tolerance="20 ppm", Manufacturer="ECS Inc.", Supplier Part Number 1=XC2151CT-ND
Y1 Y3: library part CMP-0004637-3, "Crystal, 24 MHz, 20pF, SMD", Frequency_Fixed=24MHz, Frequency Stability=+/-100ppm, Manufacturer="ECS Inc.", Supplier Part Number 1=XC1826CT-ND
Y2: library part CMP-0006147-4, "Resonator, 6 MHz, 15pF SMD", Frequency_Fixed=6MHz, Frequency Stability="+/-0.2 %", Manufacturer=MuRata, Supplier Part Number 1=490-1218-1-ND
ZZ1: library part CMP-0077236-1
ZZ2: library part CMP-0077237-1
ZZ3: library part CMP-0077238-1
ZZ4: library part CMP-0077238-1, "These assemblies must comply with workmanship standards IPC-A-610 Class 2, unless otherwise specified."

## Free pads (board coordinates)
  round 20 hole 20 unplated: 1(715.26,39.72) 1(715.26,996.48) 1(715.26,1033.93) 1(715.26,1993.82) 1(715.26,2031.27) 1(715.49,957.62) 1(715.49,1954.96) 1(715.49,2923.58) 1(715.85,76.79) 1(715.85,1071) 1(715.85,2068.34) 1(716.04,919.57) 1(716.04,1916.9) 1(716.08,2960.65) 1(764.47,39.37) 1(764.47,996.12) 1(764.47,1033.58) 1(764.47,1993.46) 1(764.47,2030.92) 1(764.7,957.27) 1(764.7,1954.6) 1(764.7,2923.23) 1(765.06,76.44) 1(765.06,1070.65) 1(765.06,2067.99) 1(765.26,919.21) 1(765.26,1916.55) 1(765.29,2960.3)
  oval 70x750 hole 70 slot 750 at 90 deg unplated: 1(741.43,499.02) 1(741.43,1496.3) 1(741.43,2501.78)

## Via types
v1: diameter 24, hole 12, Top Layer to Bottom Layer, tented both sides, 227 vias
v2: diameter 19.68, hole 7.87, Top Layer to Bottom Layer, 17 vias
v3: diameter 19.68, hole 7.87, Top Layer to Bottom Layer, tented both sides, 5 vias

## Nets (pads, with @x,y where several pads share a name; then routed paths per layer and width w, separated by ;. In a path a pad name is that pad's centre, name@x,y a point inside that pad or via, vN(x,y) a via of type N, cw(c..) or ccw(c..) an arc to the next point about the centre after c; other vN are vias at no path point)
3V3_LDO: C33.1 C34.1 C35.1 J7.1 J8.1 J9.1 R28.2 R29.2 U11.3 | length 524.8
  Top Layer w13: v1(2924.84,969.06) 2983.09,910.81 R29.2@3038.98,910.81
  Bottom Layer w12: C35.1@2919.53,1386.64 C35.1@2923.57,1390.69
  Bottom Layer w25: 2873.67,1440.58 C35.1@2923.57,1390.69 ; U11.3@2919.53,1076.34 C35.1@2919.53,1386.64
3V3_OPT: J9.2 R2.2 R3.2 R4.2 U1.5 | length 582.7
  Bottom Layer w25: J9.2@1895.91,2367.91 1895.91,2425.83 1950.39,2480.32 2177.74,2480.32 U1.5@2246.32,2411.73 ; v1(3121.65,2647.64) 3125.06,2644.23 R4.2@3125.06,2588.81 ; v1(3777.57,2621.71) 3799.1,2643.24 R3.2@3831.8,2643.24
  other v1: 2914.49,2244.78
5V: C1.1 C2.1 C27.1 C28.1 C29.1 C30.1 D3.2 L1.2 R25.2 U4.2 U5.2 U7.2 U9.2 | length 2164.1
  Top Layer w13: v1(1872.23,1249.76) 2374.2,1249.76 2377.28,1246.68 2382.01,1251.42 2371.7,1261.72 2377.28,1267.3 2377.28,1884.11
  Bottom Layer w13: R25.2@1869.28,1200.05 1869.28,1246.81 v1(1872.23,1249.76) ; v1(2649.21,2626) 2670.85,2626 2767.32,2529.53 U7.2@2767.32,2465.16
  Bottom Layer w20: L1.2@2316.54,1075 2430.2,1075 D3.2@2456.3,1048.89 ; U5.2@2895.28,2710.17 2932.15,2673.29 C2.1@2932.15,2588.81 ; U9.2@3257.7,2347.44 3257.7,2464.57 3320.9,2527.77 v1(3320.9,2677.49) ; C1.1@3557.19,2636.35 3598.34,2677.49 U4.2@3598.34,2710.17
  Bottom Layer w25: R25.2@1869.28,1200.05 R25.2@1872.23,1203
  other v1: 2389.5,1166.46 2680.86,1311.46 2680.86,1358.27 2680.86,1403.18 2574.77,1428.46 2628.54,1428.46 2522.09,1428.59
5V-12V: C18.1 C19.1 C20.1 C21.1 C22.1 C24.1 C25.1 D2.1 R24.2 U10.2 U10.10
  other v1: 1879.77,758.11 1836.56,777.56 1930.34,777.56 1879.77,804.87 1931.07,835.01 1838.62,837.48 1879.77,856.3 1838.62,884.24 1931.8,884.24 1879.77,905.51 1838.62,933.74 1958.11,1291.97 1958.11,1338.73 1958.11,1388.23 2058.57,1776.25 2058.57,1823.01 2058.57,1872.51
BC1: C58.1 R43.1 R44.1 | length 198.2
  Bottom Layer w25: R43.1@4847.75,1158.23 R44.1@4847.75,1268.39 C58.1@4847.75,1356.38
BC3: C59.1 R45.1 R46.1 | length 200.6
  Bottom Layer w13: C59.1@4941.01,1023.97 C59.1@4941.64,1023.34
  Bottom Layer w25: C59.1@4941.01,1023.97 R46.1@4941.01,1116.08 R45.1@4941.01,1223.69
C1: R44.2 T2.15 | length 225.3
  Top Layer w20: v1(4633.81,1336.2) 4634.15,1336.54 T2.15@4696.01,1336.54
  Bottom Layer w20: v1@4634.49,1336.88 v1(4633.81,1336.2) 4699.95,1336.2 R44.2@4767.75,1268.39
C2: R43.2 T2.10 | length 228.3
  Top Layer w20: v1(4632.81,1086.03) 4633.32,1086.54 T2.10@4696.01,1086.54
  Bottom Layer w20: v1(4632.81,1086.03) 4695.56,1086.03 R43.2@4767.75,1158.23
CLK_OUT: R57.1 R59.2 R108.1 U14.31 | length 1613.6
  Top Layer w9: U14.31@3577.08,1102.52 3577.08,1087.18 3594.09,1070.16
  Top Layer w13: R59.2@2380.91,423.17 R59.2@2380.91,419.54 2382.01,420.64 R57.1@2382.01,488.54 2416.93,488.54 v1(2442.52,462.95) ; 3594.09,1070.16 3596.76,1067.5 v1(3596.76,1030.72)
  Bottom Layer w13: v1(2442.52,462.95) 3029,462.95 v1(3596.76,1030.72)
CLK_OUT_EXT: J14.54 J22.56 | length 791.3
  Signal1 w13: v1(165.24,1129.92) 165.98,1130.66 169.29,1130.66 307.93,992.02 307.93,752.73 361.41,699.25 487.4,699.25 J22.56@532.28,654.36
  Bottom Layer w13: J14.54@78.74,1129.92 v1(165.24,1129.92)
CLK_OUT_S: J18.54 R108.2 | length 945
  Bottom Layer w13: R108.2@2501.57,436.97 2501.57,395.17 2532.57,364.17 3103.69,364.17 3137.2,330.66 3137.2,202.17 3109.84,174.8 J18.54@3109.84,101.18
COL: R53.1 R56.1 R97.1 U14.28 | length 1463.8
  Top Layer w9: U14.28@3517.98,1102.52 3519.59,1100.96 3519.59,1030.72 3526.68,1023.62 3526.68,1005.7 R97.1@3526.38,1005.39
  Top Layer w13: R53.1@2379.54,1058.54 R56.1@2379.54,985.18 2396.66,968.06 2792.75,968.06 2820.12,995.44 3194.73,995.44 3321.16,869 3404.37,869 3495.67,960.3 3495.67,986.75 3514.31,1005.39 R97.1@3526.38,1005.39
COL_EXT: J14.18 J22.14 | length 633.3
  Bottom Layer w13: J14.18@78.74,1696.85 154.04,1696.85 362.11,1904.92 362.11,1958.97 402.39,1999.25 477.17,1999.25 J22.14@532.28,2054.36
COL_S: J18.18 R97.2 | length 1496.8
  Top Layer w13: R97.2@3526.38,979.41 3526.38,904.27 3544.83,885.83 v1@3574.41,885.83
  Signal1 w13: v1(3571.71,884.25) 3584.25,871.71 3602.64,853.32 ccw(c3611.83,844.13) 3621.02,834.94 cw(c3630.21,825.74) 3639.41,816.55 ccw(c3648.6,807.36) 3657.79,798.17 3662.99,792.97 3684.65,771.31 3684.65,758.31 3684.65,741.38 cw(c3675.58,741.38) 3675.58,732.31 ccw(c3675.58,719.31) 3662.58,719.31 ccw(c3675.58,719.31) 3675.58,706.31 3684.65,706.31 3693.71,706.31 cw(c3693.71,693.31) 3706.71,693.31 cw(c3693.71,693.31) 3693.71,680.31 3684.65,680.31 3675.58,680.31 ccw(c3675.58,667.31) 3662.58,667.31 ccw(c3675.58,667.31) 3675.58,654.31 3684.65,654.31 3693.71,654.31 cw(c3693.71,641.31) 3706.71,641.31 cw(c3693.71,641.31) 3693.71,628.31 3684.65,628.31 3675.58,628.31 ccw(c3675.58,615.31) 3662.58,615.31 ccw(c3675.58,615.31) 3675.58,602.31 3684.65,602.31 3693.71,602.31 cw(c3693.71,589.31) 3706.71,589.31 cw(c3693.71,589.31) 3693.71,576.31 3684.65,576.31 3675.58,576.31 ccw(c3675.58,563.31) 3662.58,563.31 ccw(c3675.58,563.31) 3675.58,550.31 3684.65,550.31 3693.71,550.31 cw(c3693.71,537.31) 3706.71,537.31 cw(c3693.71,537.31) 3693.71,524.31 3684.65,524.31 3675.58,524.31 ccw(c3675.58,511.31) 3662.58,511.31 ccw(c3675.58,511.31) 3675.58,498.31 3684.65,498.31 3693.71,498.31 cw(c3693.71,485.31) 3706.71,485.31 cw(c3693.71,485.31) 3693.71,472.31 3684.65,472.31 3675.58,472.31 ccw(c3675.58,459.31) 3662.58,459.31 ccw(c3675.58,459.31) 3675.58,446.31 3684.65,446.31 3693.71,446.31 cw(c3693.71,433.31) 3706.71,433.31 cw(c3693.71,433.31) 3693.71,420.31 3684.65,420.31 3675.58,420.31 ccw(c3675.58,407.31) 3662.58,407.31 ccw(c3675.58,407.31) 3675.58,394.31 3684.65,394.31 3693.71,394.31 cw(c3693.71,381.31) 3706.71,381.31 cw(c3693.71,381.31) 3693.71,368.31 ccw(c3693.71,359.24) 3684.65,359.24 3684.65,342.31 3684.65,326.99 v1@3684.65,305.12
  Bottom Layer w13: J18.18@3676.77,78.74 3676.77,118.11 3684.05,125.39 3684.05,152.04 3693.62,161.62 3695.6,161.62 3698.24,164.25 3698.24,257.02 3684.65,270.61 3684.65,304.04 v1(3685.16,304.55)
CRS: R58.1 R60.2 R96.1 U14.29 | length 2062.7
  Top Layer w9: U14.29@3537.67,1102.52 3537.71,1045.52 R96.1@3554.92,1028.31 3554.92,1023.75 3568.31,1023.75 3575.56,1016.51
  Top Layer w13: R58.1@2379.37,208.39 R60.2@2379.37,142.92 2455.79,142.92 2521.26,208.39 2521.26,421.26 2794.12,694.12 3516.22,694.12 3642.6,820.5 3642.6,947.58 3577.56,1012.62
CRS_EXT: J14.16 J22.11 | length 683
  Bottom Layer w13: J14.16@78.74,1728.35 132.2,1728.35 334.06,1930.2 334.06,2020.7 417.13,2103.77 481.69,2103.77 J22.11@532.28,2154.36
CRS_S: J18.16 R96.2 | length 1530.2
  Top Layer w13: R96.2@3554.92,1002.32 3554.92,949.55 v1(3587.15,917.32)
  Signal1 w13: v1(3587.15,917.32) 3623.62,917.32 3627.29,913.65 cw(c3636.48,904.46) 3645.67,895.27 ccw(c3654.87,886.08) 3664.06,876.89 cw(c3673.25,867.69) 3682.44,858.5 ccw(c3691.64,849.31) 3700.83,840.12 cw(c3710.02,830.92) 3719.21,821.73 ccw(c3728.41,812.54) 3737.6,803.35 3751.57,789.37 3754.34,786.6 3754.34,778.61 ccw(c3759.35,778.61) 3759.35,773.6 cw(c3759.35,760.6) 3772.35,760.6 cw(c3759.35,760.6) 3759.35,747.6 3754.34,747.6 3749.33,747.6 ccw(c3749.33,734.6) 3736.33,734.6 ccw(c3749.33,734.6) 3749.33,721.6 3754.34,721.6 3759.35,721.6 cw(c3759.35,708.6) 3772.35,708.6 cw(c3759.35,708.6) 3759.35,695.6 3754.34,695.6 3749.33,695.6 ccw(c3749.33,682.6) 3736.33,682.6 ccw(c3749.33,682.6) 3749.33,669.6 3754.34,669.6 3759.35,669.6 cw(c3759.35,656.6) 3772.35,656.6 cw(c3759.35,656.6) 3759.35,643.6 3754.34,643.6 3749.33,643.6 ccw(c3749.33,630.6) 3736.33,630.6 ccw(c3749.33,630.6) 3749.33,617.6 3754.34,617.6 3759.35,617.6 cw(c3759.35,604.6) 3772.35,604.6 cw(c3759.35,604.6) 3759.35,591.6 3754.34,591.6 3749.33,591.6 ccw(c3749.33,578.6) 3736.33,578.6 ccw(c3749.33,578.6) 3749.33,565.6 3754.34,565.6 3759.35,565.6 cw(c3759.35,552.6) 3772.35,552.6 cw(c3759.35,552.6) 3759.35,539.6 3754.34,539.6 3749.33,539.6 ccw(c3749.33,526.6) 3736.33,526.6 ccw(c3749.33,526.6) 3749.33,513.6 3754.34,513.6 3759.35,513.6 cw(c3759.35,500.6) 3772.35,500.6 cw(c3759.35,500.6) 3759.35,487.6 3754.34,487.6 3749.33,487.6 ccw(c3749.33,474.6) 3736.33,474.6 ccw(c3749.33,474.6) 3749.33,461.6 3754.34,461.6 3759.35,461.6 cw(c3759.35,448.6) 3772.35,448.6 cw(c3759.35,448.6) 3759.35,435.6 3754.34,435.6 3749.33,435.6 ccw(c3749.33,422.6) 3736.33,422.6 ccw(c3749.33,422.6) 3749.33,409.6 3754.34,409.6 3759.35,409.6 cw(c3759.35,396.6) 3772.35,396.6 cw(c3759.35,396.6) 3759.35,383.6 3754.34,383.6 3749.33,383.6 ccw(c3749.33,370.6) 3736.33,370.6 ccw(c3749.33,370.6) 3749.33,357.6 cw(c3749.33,352.59) 3754.34,352.59 3754.34,331.6 3754.34,318.46 3722.85,286.96 v1@3722.85,272.35
  Bottom Layer w13: J18.16@3708.95,78.74 3708.95,120.76 3715.55,127.37 3715.55,152.04 3719.11,155.61 3719.11,265.67 3717.23,267.54 v1(3722.05,272.35)
D0_N: C66.1 R64.2 U15.2 | length 546.1
  Top Layer w9: U15.2@4772.94,2188.42 4772.94,2204.73 4773.78,2205.57 4773.78,2223.11 4795.52,2244.85 4854.44,2244.85 4976,2123.29 4976,2058.62 4968.55,2051.18 4968.55,2033.3 v1(4975.26,2033.3)
  Bottom Layer w9: v1(4975.26,2033.3) 4977.39,2033.3 5008.23,2002.47 5018.5,2002.47 C66.1@5035.72,2019.68 5053.45,2001.95 5078.49,2001.95 5083.77,2007.22 R64.2@5083.77,2018.93
D0_P: C67.1 R61.1 R65.2 U15.1 | length 535.5
  Top Layer w9: U15.1@4792.63,2188.42 4792.63,2204.73 4791.78,2205.57 4791.78,2215.66 4802.98,2226.85 4846.99,2226.85 4958,2115.84 4958,2066.08 4950.55,2058.63 4950.55,2007.05 4961.75,1995.85 v1(4970.28,1995.85) v1@4970.28,1994.6
  Bottom Layer w9: v1(4970.28,1995.85) 4989.38,1995.85 5014.53,1970.71 5031.22,1970.71 C67.1@5035.72,1966.21 5053.45,1983.95 5070.04,1983.95 5073.93,1980.06 5073.93,1980.12 R65.2@5094.17,1959.88
D1_N: C69.1 R67.2 U15.11 | length 178.1
  Top Layer w9: R67.2@4469.38,2119.47 4491.25,2119.47 4506.43,2134.65 4506.43,2138.45 C69.1@4510.93,2142.95 4530.42,2123.46 ; 4532.59,2122.62 4612.09,2122.62 4612.93,2123.46 U15.11@4629.24,2123.46
D1_P: C68.1 R68.2 U15.12 | length 206.5
  Top Layer w9: R68.2@4455.82,2077.99 4479.3,2101.47 4491.25,2101.47 4506.43,2086.28 4506.43,2082.49 C68.1@4510.93,2077.99 4537.56,2104.62 4612.09,2104.62 4612.93,2103.77 U15.12@4629.24,2103.77
D2_N: C73.1 R71.2 U15.15 | length 257.1
  Top Layer w9: v1(4560.15,2028.77) 4576.09,2044.72 U15.15@4629.24,2044.72
  Bottom Layer w9: R71.2@4445.97,1999.25 4464.45,1980.77 4496.4,1980.77 C73.1@4510.93,1995.31 4532.45,1973.8 4542.43,1973.8 4555.46,1986.83 4555.46,2024.08 v1(4560.15,2028.77)
D2_P: C72.1 R72.2 U15.16 | length 242.6
  Top Layer w9: v1(4579.83,1999.25) 4599.52,2018.93 4605.62,2025.03 U15.16@4629.24,2025.03
  Bottom Layer w9: R72.2@4445.97,1940.19 4459.75,1953.97 4487.31,1953.97 4507,1934.29 C72.1@4510.93,1934.29 4532.45,1955.8 4549.89,1955.8 4579.83,1985.74 v1(4579.83,1999.25)
DM3: R82.2 U15.19 | length 210.1
  Top Layer w13: R82.2@4583.77,1835.86 4583.77,1867.09 4612.5,1895.82 4612.5,1901.48 4669.41,1958.38 4670.72,1958.38 4689,1976.67 4689,1977.98 4694.2,1983.18 U15.19@4694.2,1999.44
DM4: R84.2 U15.23 | length 169
  Top Layer w9: 4772.94,1940.52 U15.23@4772.94,1999.44
  Top Layer w13: R84.2@4695.08,1862.66 4772.94,1940.52
DP3: R83.2 U15.20 | length 200.7
  Top Layer w9: 4713.89,1973.34 U15.20@4713.89,1999.44
  Top Layer w13: R83.2@4638.3,1834.91 4633.38,1839.83 4633.38,1892.83 4678.05,1937.51 4679.36,1937.51 4709.88,1968.02 4709.88,1969.33 4713.89,1973.34
DP4: R85.2 U15.24 | length 155.1
  Top Layer w9: 4792.63,1906.9 U15.24@4792.63,1999.44
  Top Layer w13: R85.2@4748.39,1862.66 4792.63,1906.9
EARTH_GND: C58.2 C59.2 C61.2 C63.2 J17.9 J17.10 J17.11 J17.12 J24.1 R51.1
EXT_REF_CLK: J16.1 R42.1 | length 447.6
  Top Layer w13: R42.1@3750.11,1375.62 3750.11,1620.62 3776.1,1646.6 3776.1,1745.84 3798.12,1767.87 3798.12,1771.87 J16.1@3820.38,1794.13
EZFET_AVBUS: C79.1 R89.1 R91.2 U16.1 | length 262.7
  Top Layer w9: R89.1@4209.75,2292.03 R89.1@4210.51,2291.28
  Top Layer w13: R89.1@4209.75,2292.03 C79.1@4209.75,2401.81 4214.16,2406.22 v1(4214.16,2480.31)
  Bottom Layer w9: v1(4214.16,2480.31) 4214.16,2497.7 4209.75,2502.11 4235.51,2527.87 U16.1@4246.94,2527.87
EZFET_AVCOUT2ADC: C80.1 R90.1 R92.2 U16.2 | length 267.6
  Top Layer w13: R90.1@4017.32,2542.87 4036.71,2523.48 4096.25,2523.48 ; R92.2@4077.86,2519.69 C80.1@4138.89,2519.69 4154.73,2535.53 v1(4194.49,2535.53)
  Bottom Layer w9: 4206.52,2547.56 U16.2@4246.94,2547.56
  Bottom Layer w13: v1(4194.49,2535.53) 4206.52,2547.56
EZFET_LED0: R86.2 U16.20 | length 371.4
  Top Layer w13: v1(4331.58,2893.7) 4637.5,2893.7 R86.2@4652.04,2879.17
  Bottom Layer w13: U16.20@4331.58,2848.74 v1(4331.58,2893.7)
EZFET_LED1: R87.2 U16.21 | length 398.5
  Top Layer w9: v1@4355.1,2785.43 4361.76,2778.77
  Top Layer w13: v1(4351.75,2791.73) 4369.94,2773.54 4457.56,2773.54 4548.78,2682.32 R87.2@4638.26,2682.32
  Bottom Layer w10: v1@4351.27,2792.21 U16.21@4351.27,2848.74
  Bottom Layer w13: v1@4351.27,2792.21 v1(4351.75,2791.73)
EZFET_PUD_N: C76.1 R76.1 U16.52 | length 626.9
  Top Layer w9: v1(4322.43,2312.99) 4322.43,2315.96 4348.34,2341.86 4483.27,2341.86 v1(4501.09,2324.04)
  Bottom Layer w9: R76.1@4304.24,2160.66 4288.64,2176.27 4288.64,2198.21 C76.1@4314.08,2223.66 4297.41,2223.66 4281.12,2239.95 4281.12,2291.28 4307.98,2318.14 4312.84,2318.14 4318.29,2323.59 4322.43,2319.44 v1(4322.43,2312.99) ; v1(4501.09,2324.04) 4501.09,2335.14 4513.89,2347.95 4513.89,2358.58 4521.99,2366.69 4521.99,2437.73 4504.06,2455.66 4504.06,2475.86 4508.75,2480.55 U16.52@4508.75,2499.23
EZFET_PUD_P: C75.1 R77.1 R80.1 R81.2 U16.50 | length 656.2
  Top Layer w9: v1(4302.75,2342.51) 4317.97,2342.51 4320.63,2339.86 4335.48,2354.71 4335.61,2354.59 4340.88,2359.86 4490.73,2359.86 4496,2354.59 4534.29,2354.59 v1(4540.46,2348.42)
  Bottom Layer w9: R81.2@4252.99,2284.68 R81.2@4256.52,2284.68 ; R80.1@4255.03,2160.66 4270.64,2176.27 4270.64,2194.56 C75.1@4241.54,2223.66 4263.12,2245.23 4263.12,2284.68 R81.2@4256.52,2284.68 ; v1(4302.75,2342.51) 4302.75,2341.36 v1@4304.24,2339.86 ; v1@4309.51,2345.13 4263.12,2298.73 4263.12,2291.28 R81.2@4256.52,2284.68 ; 4539.99,2437.73 4539.99,2442.85 4552.81,2455.66 4552.81,2475.86 4548.12,2480.55 U16.50@4548.12,2499.23 ; 4540.27,2435.78 4539.99,2436.06 4539.99,2348.89 v1(4540.46,2348.42)
EZFET_PUR: R77.2 U16.51 | length 151.1
  Top Layer w9: v1(4528.43,2465.76) v1(4588.19,2465.78)
  Bottom Layer w9: v1(4528.43,2465.76) U16.51@4528.43,2502.28
  Bottom Layer w13: v1(4588.19,2465.78) 4588.19,2431.48 R77.2@4602.7,2416.96
EZFET_RST: C83.1 J20.1 R93.1 U16.64 | length 2999.3
  Top Layer w13: R93.1@4294.4,2619.33 4286.84,2611.76 v1(4286.84,2535.53) 4325.99,2535.53 C83.1@4339.67,2549.21
  Signal1 w13: J20.1@1630.93,2813.39 1681.72,2864.17 1839.94,2864.17 2114.01,2590.11 4174.38,2590.11 4202.58,2561.9 4205.41,2561.9 4220.86,2546.45 4220.86,2543.62 4228.96,2535.53 v1(4286.84,2535.53)
  Bottom Layer w9: U16.64@4272.53,2502.28 4272.53,2521.22 v1(4286.84,2535.53)
EZFET_SBW_RST: R95.1 U16.43 | length 305.6
  Bottom Layer w9: U16.43@4593.39,2626.3 4683.27,2626.3
  Bottom Layer w13: 4683.27,2626.3 4783.67,2525.9 R95.1@4857.39,2525.9
EZFET_SBW_TST: R94.1 U16.44 | length 262.8
  Bottom Layer w9: U16.44@4593.39,2606.61 4662.76,2606.61
  Bottom Layer w13: 4662.76,2606.61 R94.1@4799.52,2469.85
EZFET_TEST: J20.3 U16.59 | length 2814.4
  Signal1 w13: J20.3@1728.8,2811.25 1763.84,2776.21 1850.22,2776.21 2072.64,2553.8 4141.75,2553.8 4168.11,2527.43 4168.11,2524.6 4183.56,2509.15 4205.41,2509.15 4207.41,2511.15 4219.68,2511.15 4224.15,2506.68 4225.09,2506.68 4240.54,2491.23 4240.54,2490.3 4265.08,2465.76 v1(4351.75,2465.76)
  Bottom Layer w9: v1(4351.75,2465.76) 4370.95,2484.97 U16.59@4370.95,2502.28
EZFET_UARTCTS: U16.32
EZFET_UARTRTS: U16.33
EZFET_UARTRXD: U16.38
EZFET_UARTTXD: U16.37
EZFET_VREF: C78.1 U16.9 | length 116.6
  Bottom Layer w9: 4209.83,2685.35 U16.9@4246.94,2685.35
  Bottom Layer w13: C78.1@4153.65,2629.17 4209.83,2685.35
EZFET_VUSB: C84.1 U16.54 | length 113.8
  Top Layer w9: v1(4479.92,2450.79) 4501.09,2429.62 C84.1@4501.09,2401.57
  Bottom Layer w9: U16.54@4469.38,2502.28 4469.38,2461.33 v1(4479.92,2450.79)
EZFET_XIN: C91.1 U16.57 Y3.3 | length 468.1
  Bottom Layer w9: 4410.32,2454.08 U16.57@4410.32,2502.28
  Bottom Layer w13: Y3.3@4203.17,2345.03 4213.52,2355.38 4236.8,2355.38 4247.66,2366.23 4286.56,2366.23 4299.42,2379.09 4314.81,2379.09 4349.41,2344.48 4349.41,2343.72 4350.27,2342.87 4350.27,2325.68 4357.25,2318.7 4421.56,2318.7 4435.91,2333.06 C91.1@4435.91,2403.49 4435.91,2428.49 4410.32,2454.08
EZFET_XOUT: R38.2 U16.58 | length 95.8
  Bottom Layer w9: 4390.64,2427.7 U16.58@4390.64,2502.28
  Bottom Layer w13: R38.2@4375.6,2412.67 4390.64,2427.7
